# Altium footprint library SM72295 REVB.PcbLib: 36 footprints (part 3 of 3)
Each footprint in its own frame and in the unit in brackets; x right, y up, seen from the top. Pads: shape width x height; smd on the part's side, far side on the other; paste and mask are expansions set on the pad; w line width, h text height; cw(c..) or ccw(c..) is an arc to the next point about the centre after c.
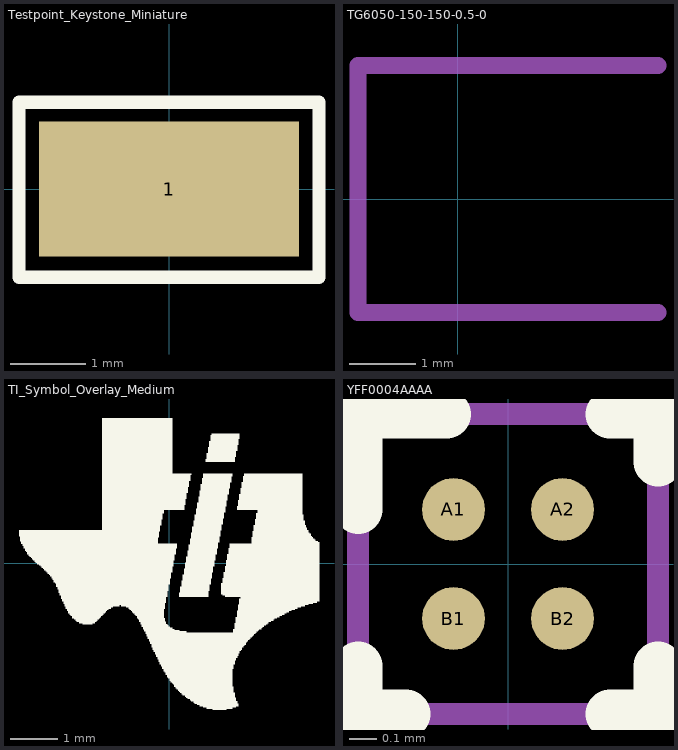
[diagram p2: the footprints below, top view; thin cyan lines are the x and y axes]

## Testpoint_Keystone_Miniature [mil] "Miniature SMT test point"
height 90.55
pads (1):
  rect 135x70 smd: 1(0,0)
Top Overlay:
  lines w7: -78,-46 -78,-38 -78,45 -65,45 5,45 78,45 78,-46 -78,-46
Mechanical 5:
  lines w5: -78,-46 78,-46 78,45 5,45 -65,45 -78,45 -78,-38 -78,-46
  text ".Designator" at 70,15 h40
3D body: height 60.6, standoff 0.6, extent -52.5,-20 52.5,20

## TG6050-150-150-0.5-0 [mil] "IGLOBAL TECHNOLOGY TG SERIES SHEET 150X150X0.5MM"
height 39.37
Mechanical 5:
  lines w10: 118.11,-66.93 -59.06,-66.93 -59.06,78.74 118.11,78.74
  text ".Designator" at 0,-3.94 h30

## TI_Symbol_Overlay_Medium [mil]
Top Overlay:
  drawing of 3 lines, arcs and shapes, not listed

## YFF0004AAAA [mm] "TI DSBGA 0.790x0.790mm"
height 0.625
pads (4):
  round 0.23 smd paste-0.13 mask+0.04: A1(-0.2,0.2) A2(0.2,0.2) B1(-0.2,-0.2) B2(0.2,-0.2)
Top Overlay:
  lines w0.18: -0.55,-0.375 -0.55,-0.55 -0.375,-0.55 ; -0.55,0.2 -0.55,0.55 -0.225,0.55 ; 0.375,-0.55 0.55,-0.55 0.55,-0.375 ; 0.375,0.55 0.55,0.55 0.55,0.375
Top Paste:
  circle w0.05: c-0.125,-0.275 r0.025
  circle w0.05: c-0.275,-0.125 r0.025
  circle w0.05: c-0.125,-0.125 r0.025
  circle w0.05: c-0.275,-0.275 r0.025
  circle w0.05: c-0.275,0.125 r0.025
  circle w0.05: c-0.125,0.275 r0.025
  circle w0.05: c-0.275,0.275 r0.025
  circle w0.05: c-0.125,0.125 r0.025
  circle w0.05: c0.275,-0.275 r0.025
  circle w0.05: c0.125,-0.125 r0.025
  circle w0.05: c0.275,-0.125 r0.025
  circle w0.05: c0.125,-0.275 r0.025
  circle w0.05: c0.125,0.125 r0.025
  circle w0.05: c0.275,0.275 r0.025
  circle w0.05: c0.125,0.275 r0.025
  circle w0.05: c0.275,0.125 r0.025
  region: -0.325,-0.125 -0.325,-0.275 -0.275,-0.275 -0.275,-0.125
  region: -0.125,-0.075 -0.275,-0.075 -0.275,-0.125 -0.125,-0.125
  region: -0.075,-0.275 -0.075,-0.125 -0.125,-0.125 -0.125,-0.275
  rectangle: -0.275,-0.325 -0.125,-0.275
  region: -0.125,-0.125 -0.275,-0.125 -0.275,-0.275 -0.125,-0.275
  region: -0.125,0.275 -0.275,0.275 -0.275,0.125 -0.125,0.125
  rectangle: -0.275,0.075 -0.125,0.125
  region: -0.075,0.125 -0.075,0.275 -0.125,0.275 -0.125,0.125
  region: -0.125,0.325 -0.275,0.325 -0.275,0.275 -0.125,0.275
  region: -0.325,0.275 -0.325,0.125 -0.275,0.125 -0.275,0.275
  region: 0.075,-0.125 0.075,-0.275 0.125,-0.275 0.125,-0.125
  region: 0.275,-0.075 0.125,-0.075 0.125,-0.125 0.275,-0.125
  region: 0.325,-0.275 0.325,-0.125 0.275,-0.125 0.275,-0.275
  rectangle: 0.125,-0.325 0.275,-0.275
  region: 0.275,-0.125 0.125,-0.125 0.125,-0.275 0.275,-0.275
  region: 0.275,0.275 0.125,0.275 0.125,0.125 0.275,0.125
  rectangle: 0.125,0.075 0.275,0.125
  region: 0.325,0.125 0.325,0.275 0.275,0.275 0.275,0.125
  region: 0.275,0.325 0.125,0.325 0.125,0.275 0.275,0.275
  region: 0.075,0.275 0.075,0.125 0.125,0.125 0.125,0.275
Mechanical 5:
  circle w0.06: c-0.2,0.2 r0.08
  lines w0.08: -0.55,-0.55 0.55,-0.55 0.55,0.55 -0.55,0.55 -0.55,-0.55
  text ".Designator" at -0.2,-0.254 h0.25
3D body: height 0.63, standoff 0, extent -0.394,-0.394 0.394,0.394
3D body: height 0.63, standoff 0.6, extent -0.286,0.114 -0.114,0.286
